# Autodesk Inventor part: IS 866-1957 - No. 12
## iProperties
Created: 2005-01
Part Number: IS 866-1957 - No. 12
Material: Steel, Mild
Description: Flat Head Rivet
Vendor: Autodesk Inc.
Document SubType Name: Modeling
Standard: IS 866-1957
Designer: Dale Schneider
Standards Organization: IS
Language: en-US
Size Designation: No. 12
Categories: <MemberInstance><Categories><Category DisplayName="Fasteners" InternalName="e4da775c-781d-43d5-af7c-5136215cf5a6" Mnemonic="FSTN"><Category DisplayName="Rivets"
Density: 1 g/cm^3
Author: Dale Schneider
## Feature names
1. Body [Revolution]
2. Fillet1
3. Fillet2
4. Fillet3
5. Fillet4
